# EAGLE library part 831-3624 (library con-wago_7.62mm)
Serie 831, Stiftleiste (für Leiterplatten) mit abgewinkelten Einlötstiften / Series 831, Male header (for PCBs) with angled solder pins Polzahl / Pole No.: 4 Bemessungsspannung / Rated Voltage: 630 V Nennstrom / Nominal Current: 41 A Lötstiftlänge: / Solder Pin Length: 4 mm Farbe / Color: lichtgrau / light gray Stand: 01.01.2012. Die jeweils aktuellen Daten zu diesem Artikel finden Sie in unserem Produktkatalog, den Sie unter www.wago.com einsehen können. As of: 01/01/2012. Please find the newest data for this article in our product catalogue, which can be viewed under www.wago.com.
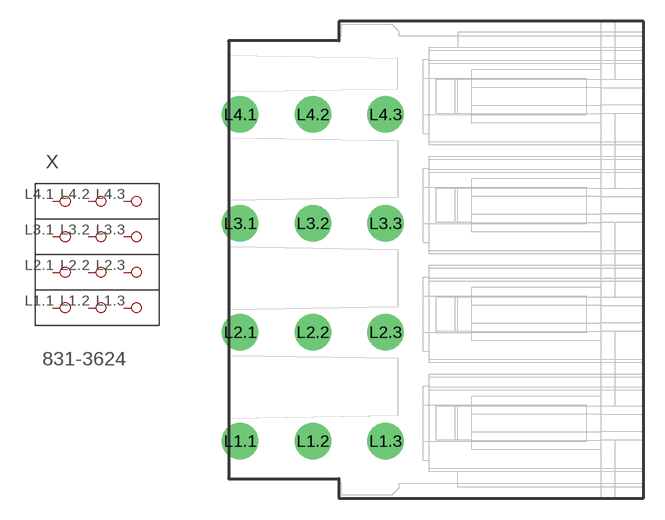
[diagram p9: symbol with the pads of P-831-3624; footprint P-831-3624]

Designator prefix X

## 831-3624  [P-831-3624]
L1.1  P1.1
L1.2  P1.2
L1.3  P1.3
L2.1  P2.1
L2.2  P2.2
L2.3  P2.3
L3.1  P3.1
L3.2  P3.2
L3.3  P3.3
L4.1  P4.1
L4.2  P4.2
L4.3  P4.3

## Footprint P-831-3624 (pad centres in mm)
drill 1.7 round: L1.1 -13.7,-12.68; L1.2 -8.62,-12.68; L1.3 -3.54,-12.68; L2.1 -13.7,-5.06; L2.2 -8.62,-5.06; L2.3 -3.54,-5.06; L3.1 -13.7,2.56; L3.2 -8.62,2.56; L3.3 -3.54,2.56; L4.1 -13.7,10.18; L4.2 -8.62,10.18; L4.3 -3.54,10.18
